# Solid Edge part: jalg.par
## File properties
Author: Mac
Template: Normal.par
Last saved by: Mac
Revision: 2
Application: Solid Edge
Material: Aluminum, 1060
Face Style: Aluminum
Fill Style: ANSI38(Aluminum)
Virtual Style: Polished aluminum
Coef. of Thermal Exp: 2.3e-05
Thermal Conductivity: 221.0
Specific Heat: 920.0
Modulus of Elasticity: 68947570000.0
Poission's Ratio: 0.33
Yield Stress: 27579028.0
Ultimate Stress: 68947570.0
Elongation: 0.0
Density: 2712,000 kg/m^3
Accuracy: 0,990
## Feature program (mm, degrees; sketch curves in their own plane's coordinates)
sketch for "unnamed Protrusion 1" #1 plane through (0, 0, 0) normal (0, 0, 1) x-axis (1, 0, 0)
  circle centre (0, 0) radius 0.64
sketch for "unnamed Protrusion 1" #2 plane through (0, 0, 0) normal (0, 0, 1) x-axis (1, 0, 0)
  line (-0.7038, 1) -> (0.7, 1)
  arc centre (0.7, 0.7) radius 0.3 from (0.7, 1) to (1, 0.7) cw
  line (1, 0.7) -> (1, -0.7)
  arc centre (0.7, -0.7) radius 0.3 from (1, -0.7) to (0.7, -1) cw
  line (0.7, -1) -> (-0.7, -1)
  arc centre (-0.7, -0.7) radius 0.3 from (-0.7, -1) to (-1, -0.7) cw
  line (-1, -0.7) -> (-1, 0.7038)
  arc centre (-0.7038, 0.7038) radius 0.2962 from (-0.7038, 1) to (-1, 0.7038) ccw
  dimension (linear) = 0.7
extrude "unnamed Protrusion 1" add finite 12.8006 along +normal
sketch for "ExtrudedCutout_2" plane through (0, 0, 0) normal (1, 0, 0) x-axis (0, 1, 0)
  line (-1.3808, 1.4469) -> (-1.3808, 1.3627)
  line (1.5168, 1.2095) -> (1.5168, 1.3036)
extrude "ExtrudedCutout_2" cut finite 7.2229 symmetric
sketch for "ExtrudedProtrusion_4" plane through (0, 0, 2.5999) normal (0, 0, 1) x-axis (1, 0, 0)
  circle centre (0, 0) radius 0.7005
extrude "ExtrudedProtrusion_4" add along +normal  Profile_Plane1_Distance = 2.5999 mm
sketch for "unnamed RevolvedProtrusion 1" plane through (0, 0, 0) normal (0, 0, 1) x-axis (1, 0, 0)
  bspline degree 3 poles (0.5443, -0.0037) (0.5435, -0.0965) (0.4896, -0.1655) (0.4163, -0.2091) (0.3418, -0.2533) (0.2473, -0.2713) (0.1328, -0.2754) (0.1226, -0.2755) (0.1123, -0.2756) knots 0 0.6423 0.9685 1 multiplicities 4 3 2 4
  line (-0.9869, -0.2756) -> (0.1123, -0.2756)
  arc centre (-0.9869, -0.2238) radius 0.0518 from (-0.9869, -0.2756) to (-1.0387, -0.2238) cw
  line (-1.0387, -0.0037) -> (-1.0387, -0.2238)
revolve "unnamed RevolvedProtrusion 1" add full turn 360 deg about sketch line (-1.0387, -0.0037) -> (0.5443, -0.0037)
sketch for "unnamed Protrusion 2" plane through (0, 0, 1.94) normal (0, 0, 1) x-axis (1, 0, 0)
  arc centre (-0.4261, 0) radius 0.0635 from (-0.4632, 0.0515) to (-0.4632, -0.0515) ccw
  bspline degree 3 poles (0.4944, 0) (0.4933, -0.2931) (-0.1281, -0.2924) (-0.4632, -0.0515) knots 0 1 multiplicities 4 4
  bspline degree 3 poles (0.4944, 0) (0.4933, 0.2931) (-0.1281, 0.2924) (-0.4632, 0.0515) knots 0 1 multiplicities 4 4
extrude "unnamed Protrusion 2" add to key point along -normal
thinwall "Thinwall_2"  Thickness = 0.06 mm
sketch for "ExtrudedProtrusion_7" plane through (-1.0387, -0.0037, 0) normal (-1, 0, 0) x-axis (0, -1, 0)
  circle centre (0, 0) radius 0.05
extrude "ExtrudedProtrusion_7" add finite 0.2552 along +normal
fillet "Round_1" radius 0.06
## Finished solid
Body 1: solid body, 40 faces, 80 edges, 44 vertices.
  Faces by surface: cylinder 14, blend 11, plane 8, offset 3, swept 2, spun 1, torus 1
  Edges by curve: intersection 38, circle 21, line 17, curve on surface 4
Bounding box of the edges (mm; curved faces can reach further): 2.294 x 2.000 x 2.872, from (-1.2939, -1, -0.2719) to (1, 1, 2.5999).
Cylindrical faces by radius (mm): R0.0035 x1, R0.05 x1, R0.0635 x1, R0.2119 x1, R0.2719 x1, R0.2962 x1, R0.3 x3, R0.6405 x1, R0.7005 x1, R1.94 x1, R2 x2
Toroidal faces (ring radius, tube radius in mm): R0.2201 r0.0518 x1
Planar faces by outward normal: +x 2, +y 1, +z 1, -x 3, -y 1
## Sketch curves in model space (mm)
arc centre (-0.4261, 0, 1.94) radius 0.0635 from (-0.4632, 0.0515, 1.94) through (-0.4896, 0, 1.94) to (-0.4632, -0.0515, 1.94)
spline (0.4944, 0, 1.94) -> (0.1409, -0.226, 1.94) -> (-0.4632, -0.0515, 1.94)
spline (0.4944, 0, 1.94) -> (0.1409, 0.226, 1.94) -> (-0.4632, 0.0515, 1.94)
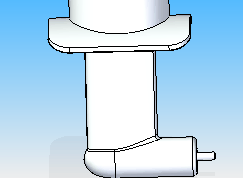
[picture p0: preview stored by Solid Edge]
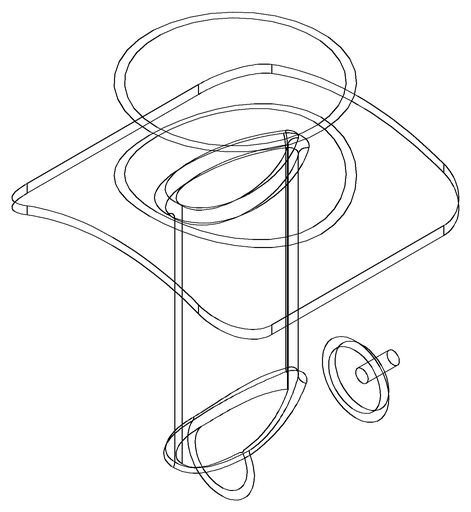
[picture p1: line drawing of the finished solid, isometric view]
